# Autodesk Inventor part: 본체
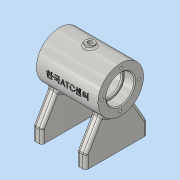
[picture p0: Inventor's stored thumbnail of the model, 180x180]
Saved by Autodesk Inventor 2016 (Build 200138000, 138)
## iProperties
Created: 2018-05
Part Number: 본체
Material: 알루미늄 6061
Document SubType Name: Modeling
Designer: Administrator
Density: 2.7 g/cm^3
Appearance: 알루미늄 - 평지
Mass: 317.681 g
Surface Area: 375.828 cm^2
Volume: 117.66 cm^3
Author: Administrator
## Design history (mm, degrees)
sketch "스케치1"
  geometry: L1 (-25, 0)-(0, 0); L2 (-20, 35)-(-30, 35); L3 (-30, 35)-(-30, -35); L4 (-30, -35)-(-20, -35); L5 (-20, -35)-(-20, 35); L6 (-20, 35)-(-30, -35); L7 (-30, 35)-(-20, -35)
  constraints: 14 end point, 2 horizontal, 2 midpoint, 2 parallel, 1 perpendicular
  dimensions: "d0" = 25 distance of L1.start L1.end; "d1" = 10 distance of L4.end L3.end; "d2" = 70 distance of L3.end L2.end
extrude "돌출1" new body sketch "스케치1" distance "d3" = 15; taper "d4" = 0 deg
sketch "스케치2"
  geometry: L1 (35, 65)-(-35, 65); L2 (35, 65)-(35, 91); L3 (35, 91)-(-35, 91); L4 (-35, 91)-(-35, 65); 2 further points
  constraints: 8 end point, 2 perpendicular, 1 horizontal, 1 midpoint, 1 vertical, 1 vertical alignment
  dimensions: "d5" = 65 distance from line of point (0, 0) L1; "d6" = 70 distance of L1.start L1.end; "d7" = 52 diameter of L3 L1
revolve "회전1" sketch "스케치2" stored, may be unused: angle "d8" = 90 deg
node "작업 평면1"
sketch "스케치3"
  geometry: L1 (-35, 15)-(35, 15) reference; L2 (-35, 15)-(-16.972, 46.226); L3 (-35, 0)-(-35, 15) reference; L4 (0, 0)-(0, 66.177); L5 (35, 15)-(16.972, 46.226); L6 (-35, 15)-(35, 15); L7 (-16.972, 46.226)-(16.972, 46.226)
  constraints: 10 end point, 1 collinear, 1 perpendicular, 1 symmetric about line, 1 vertical
  dimensions: "d10" = 30 deg angle of L3 L2
extrude "돌출2" join sketch "스케치3" stored distance "d11" = 10; taper "d12" = 0 deg
sketch "스케치4"
  geometry: L1 (35, 39)-(35, 91) reference; L2 (35, 65)-(-35, 65); L3 (-35, 39)-(-35, 91) reference; L4 (-35, 39)-(35, 39) reference; L5 (0, 39)-(0, 91); L6 (35, 65)-(35, 81); L7 (35, 81)-(23, 81); L8 (23, 81)-(23, 79); L9 (23, 79)-(21, 79); L10 (21, 79)-(21, 86); L11 (21, 86)-(0, 86); L12 (-23, 79)-(-21, 79); L13 (-35, 65)-(-35, 81); L14 (-35, 81)-(-23, 81); L15 (-23, 81)-(-23, 79); L16 (-21, 79)-(-21, 86); L17 (-21, 86)-(0, 86); 1 further point
  constraints: 28 end point, 5 symmetric about line, 4 perpendicular, 3 midpoint, 2 point on line, 1 horizontal, 1 vertical
  dimensions: "d13" = 32 diameter of L7 L2; "d14" = 28 diameter of L9 L2; "d15" = 42 diameter of L11 L2; "d16" = 12 distance of L6.end L7.end; "d17" = 21 distance of L10.end L11.end
revolve "회전2" sketch "스케치4" stored, may be unused: angle "d18" = 90 deg
node "작업 평면2"
sketch "스케치5"
  geometry: C1 r 5 at (0, 0); 1 further point
  constraints: 1 centre point, 1 coincident
  dimensions: "d20" = 10 diameter of C1
extrude "돌출3" join sketch "스케치5" stored distance "d21" = 10; taper "d22" = 0 deg
sketch "스케치6" dims "d23" = 42
  geometry: 4 further points
  constraints: 2 horizontal alignment, 4 other
hole "구멍1" sketch "스케치6" at (-20.993, 0.536) diameter "d24" = 3.242; stored, may be unused: countersink angle "d28" = 90 deg, drill point angle "d30" = 118 deg; dims "d25" = 8, "d26" = 4, "d27" = 2, "d29" = 10
sketch "스케치7"
  geometry: 2 further points
  dimensions: "d34" = 20 vertical distance of point (30, -35) point (5, -55)
hole "구멍2" sketch "스케치7" at (5, -55) diameter "d35" = 4.134; stored, may be unused: countersink angle "d39" = 90 deg, drill point angle "d41" = 118 deg; dims "d36" = 8, "d37" = 4, "d38" = 2, "d40" = 10
sketch "스케치8"
  geometry: L1 (0, 65)-(8.893, 40.568); L2 (0, 65)-(0, 57.633); 2 further points
  constraints: 4 end point, 1 coincident, 1 vertical, 2 other
  dimensions: "d48" = 20 deg angle of L1 L2
node "작업 평면4"
  node "작업 평면3"
sketch "스케치9"
  geometry: C1 r 6 at (0, 0); 1 further point
  constraints: 1 centre point
  dimensions: "d50" = 12 diameter of C1
extrude "돌출4" join sketch "스케치9" stored distance "d51" = 10; taper "d52" = 0 deg
hole "구멍3" diameter "d55" = 5.188; stored, may be unused: countersink angle "d59" = 90 deg, drill point angle "d61" = 118 deg; dims "d53" = 10, "d54" = 10, "d56" = 12, "d57" = 4, "d58" = 2, "d60" = 16
hole "구멍4" diameter "d64" = 5.188; stored, may be unused: countersink angle "d68" = 90 deg, drill point angle "d70" = 118 deg; dims "d62" = 10, "d63" = 10, "d65" = 12, "d66" = 4, "d67" = 2, "d69" = 16
node "작업 평면5"
sketch "스케치10"
  geometry: 2 further points
  constraints: 1 other
feature "엠보싱1" sketch "스케치10" dims "d71" = 0.5, "d72" = 0
fillet "모깎기1" dims "d73" = 2, "d74" = 3
chamfer "모따기1" distance "d75" = 1; stored, may be unused: second distance "d76" = 2, angle "d77" = 45 deg
fillet "모깎기2" dims "d78" = 3, "d79" = 0.3
node "솔리드1"
mirror "대칭1"
mirror "대칭2"
pattern_circular "원형 패턴1" dims angle "d32" = 360 deg
mirror "대칭3"
pattern_linear "직사각형 패턴1" dims "d44" = 40
other parameters: "d9" = 25, "d19" = 94, "d49" = 3
